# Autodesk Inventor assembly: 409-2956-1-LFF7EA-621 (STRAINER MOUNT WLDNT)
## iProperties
Created: 2010-06
Part Number: 409-2956-1-LFF7EA-621 (STRAINER MOUNT WLDNT)
Document SubType Name: Weldment
Designer: S. Boerckel
Weld Material: Welded Aluminum-6061
Mass: 23301.6 g
Surface Area: 4922.08 cm^2
Volume: 2964.58 cm^3
Density: 7.86 g/cm^3
Description: STRAINER MOUNT
Material: WELDMENT
SMR: =<Material>
Author: S. Boerckel
Revision Number: 0
Subject: DEMIN WATER FORWARDING PUMP SKID-7EA
